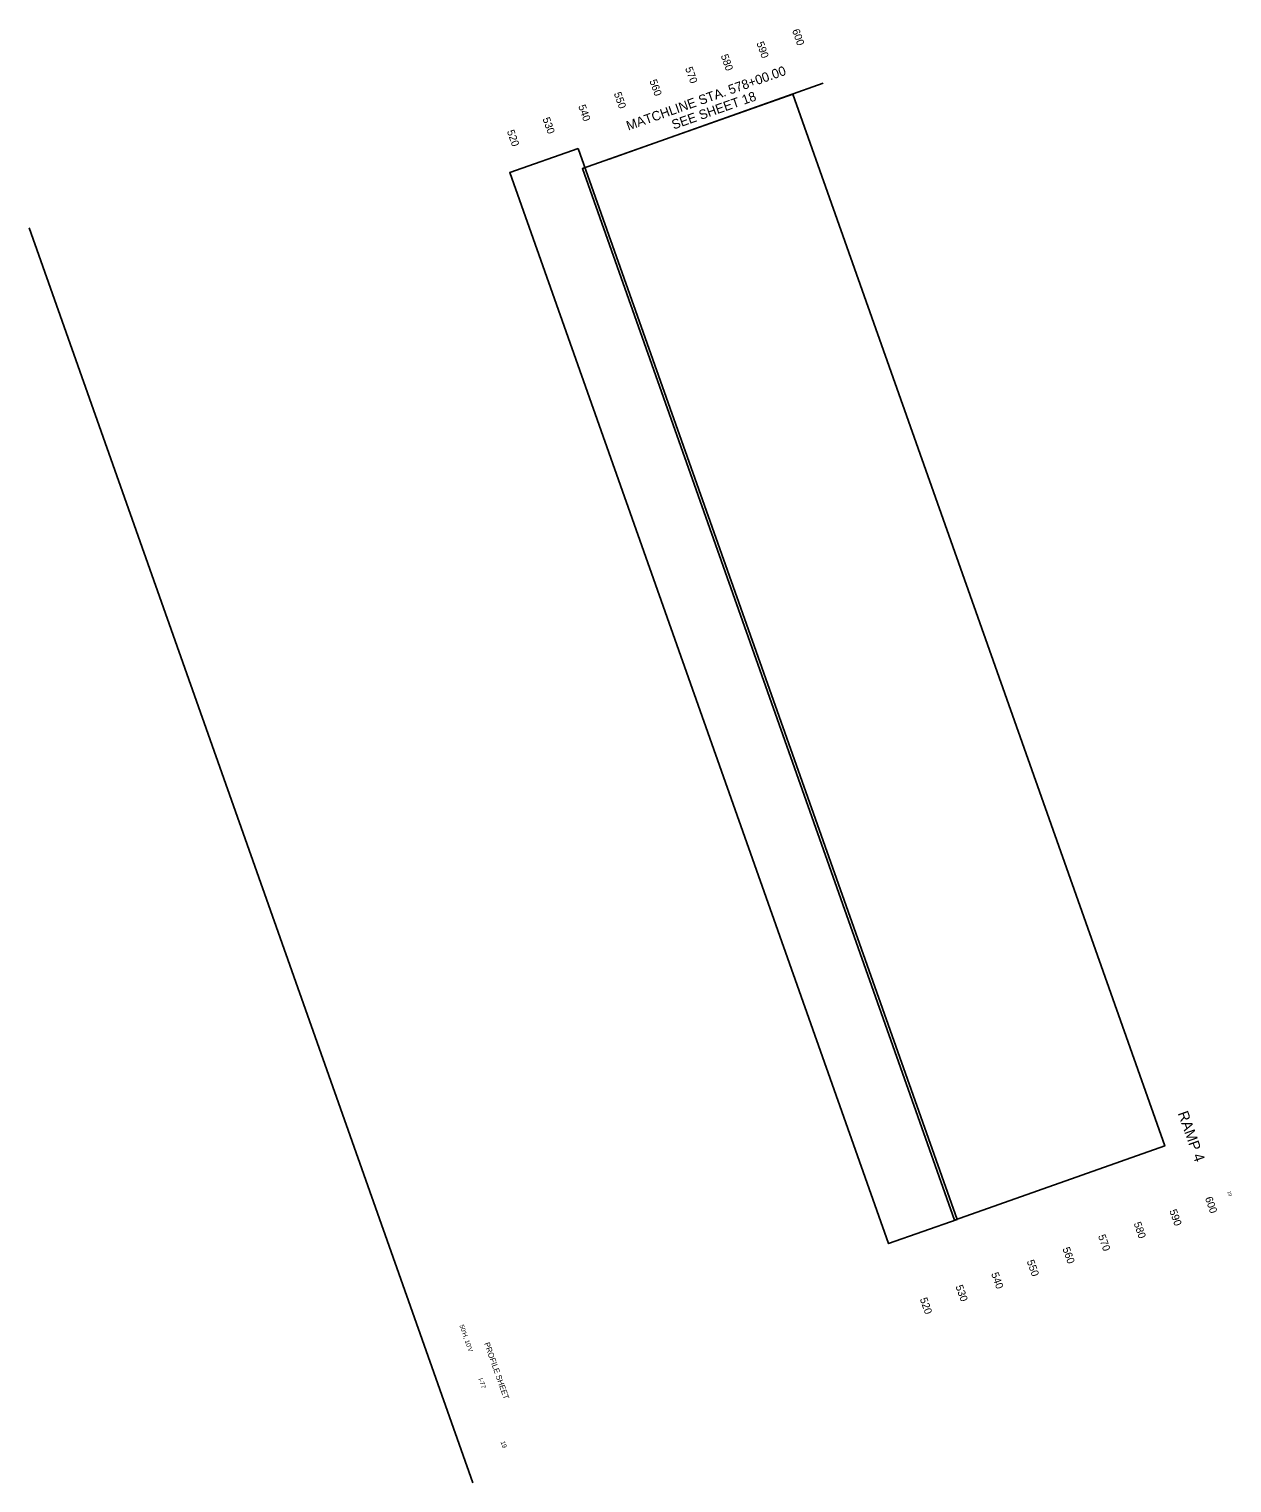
# Model space of a CAD drawing. Extents: x 1985850 to 1991973, y 1123646 to 1127638.
import ezdxf

# ---------------------------------------------------------------- set-up
doc = ezdxf.new("R2010")
doc.units = 0
for name, color, linetype in [('RD_DDB_ElevTX', 7, 'Continuous'), ('RD_SHT_MatchLine', 7, 'Continuous'), ('RD_SHT_ShtClip', 7, 'Continuous'), ('RD_SHT_TX', 7, 'Continuous')]:
    doc.layers.add(name, color=color, linetype=linetype)

msp = doc.modelspace()

# ---------------------------------------------------------------- linework, layer by layer
at = {"layer": 'RD_SHT_MatchLine'}
msp.add_line((1986900.6, 1125496.2), (1986617.7, 1125396.1), dxfattribs=at)
at = {"layer": 'RD_SHT_ShtClip'}
for points in [[(1986860.4, 1125482), (1987352.3, 1124091.4), (1987074.1, 1123993), (1986582.2, 1125383.5)], [(1986576.7, 1125410.1), (1987077.6, 1123994.2), (1986987, 1123962.2), (1986486.1, 1125378.1)]]:
    msp.add_lwpolyline(points, close=True, dxfattribs=at)
at = {"layer": 'RD_SHT_TX'}
msp.add_line((1985850.3, 1125305.1), (1986437.3, 1123645.8), dxfattribs=at)

# ---------------------------------------------------------------- texts
at = {"layer": 'RD_DDB_ElevTX'}
for s, p in [('600', (1986859.3, 1125566.1)), ('590', (1986812.2, 1125549.4)), ('580', (1986765, 1125532.7)), ('570', (1986717.9, 1125516)), ('550', (1986623.6, 1125482.7)), ('560', (1986670.7, 1125499.4)), ('540', (1986576.5, 1125466)), ('530', (1986529.3, 1125449.3)), ('520', (1986482.2, 1125432.7)), ('600', (1987405.4, 1124022.3)), ('590', (1987358.3, 1124005.6)), ('580', (1987311.1, 1123989)), ('570', (1987264, 1123972.3)), ('560', (1987216.9, 1123955.6)), ('550', (1987169.7, 1123938.9)), ('530', (1987075.5, 1123905.6)), ('540', (1987122.6, 1123922.3)), ('520', (1987028.3, 1123888.9))]:
    msp.add_text(s, height=10, rotation=289.482, dxfattribs=at).set_placement(p)
at = {"layer": 'RD_SHT_MatchLine'}
for s, p in [('MATCHLINE STA. 578+00.00', (1986642.9, 1125433.6)), ('SEE SHEET 18', (1986702.9, 1125435))]:
    msp.add_text(s, height=12.5, rotation=19.482, dxfattribs=at).set_placement(p)
at = {"layer": 'RD_SHT_TX'}
for s, height, p in [('RAMP 4', 14, (1987369.4, 1124134.6)), ('19', 4.5, (1987435, 1124030.9)), ("50'H, 10'V", 6, (1986419.4, 1123853.9)), ('PROFILE SHEET', 7.5, (1986452.1, 1123830.2)), ('I-77', 6, (1986444.4, 1123783.3)), ('19', 6, (1986473.8, 1123700))]:
    msp.add_text(s, height=height, rotation=289.482, dxfattribs=at).set_placement(p)

doc.saveas('drawing.dxf')
